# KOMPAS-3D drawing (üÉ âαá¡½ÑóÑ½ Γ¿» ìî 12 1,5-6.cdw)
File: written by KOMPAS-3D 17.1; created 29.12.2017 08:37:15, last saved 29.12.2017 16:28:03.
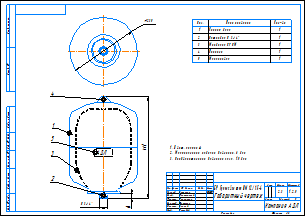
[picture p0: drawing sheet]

Sheet 1: A3, landscape, title-block layout from C:\Лощинин\GRAPHIC.LYT style 1

Title block, sheet 1: name: БР Гранлевел тип НМ 12/1,5-6 / Габаритный чертеж; mass: 2,3; scale: 1:2,5; sheets: 1; sheet format: A3; stored path: K:\АП\20_PKO\02_Насосное направление\Разработка\04_Проекты разные\Баки\КД действующая\Баки Flexcon R\Компас\Чертежи\БР Гранлевел тип НМ 12 1,5-6.cdw; drawn by: Лощинин; checked by: Хантимеров; drawn by, date: 29.12.2017

Views: Проекционный вид 2
Referenced files in \\Fsk1\files\АП\20_PKO\02_Насосное направление\Разработка\04_Проекты разные\Баки\КД действующая\Баки Flexcon R\Компас\: 12 литров.a3d
Referenced files in C:\Лощинин\: GRAPHIC.LYT
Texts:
  IvAn
  ADL
  Цвет: красный
  Максимальное рабочее давление: 6 бар
  Предварительное давление газа: 1,5 бар
  Лит-Масса-Масштаб
  Материал-Предприятие
  Масштаб
  Изм.
  Лист
  № докум.
  Подп.
  Дата
  Лит.
  Разраб.
  Пров.
  Т.контр.
  Курлыкина
  Листов
  Нач.отд.
  Щетинин
  Н.контр.
  Долгов
  Утв.
  Рашидов
  Компания АДЛ
  Изменение
  Номер документа
  Подпись
  Обозначение документа
  Наименование изделия
  Масса изделия по ГОСТ 2.109-73
  Порядковый номер листа
  Общее количество листов в документе
  Характер работы, выполненной лицом, подписавшим документ
  Наименование или индекс предприятия, выпускающего документ
  Инв. № подл.
  Подп. и дата
  Взам. инв. №
  Инв. № дубл.
  Инвентарный номер подлинника по ГОСТ 2.501-68
  Подпись принявшего подлинник в отдел технической документации
  Инвентарный номер подлинника, взамен которого выпущен данный подлинник
  Инвентарный номер дубликата по ГОСТ 2.502-68
  Подпись принявшего дубликат в отдел технической документации
  Справ. №
  Перв. примен.
  Обозначение документа, взамен или на основании которого выпущен данный документ
  Обозначение документа, в котором впервые записан данный документ
  Подпись лица, копировавшего чертеж
  Обозначение формата листа
Dimensions and other numbers on the sheet: 235; 1:2,5; 1; 2,3; 29.12.2017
